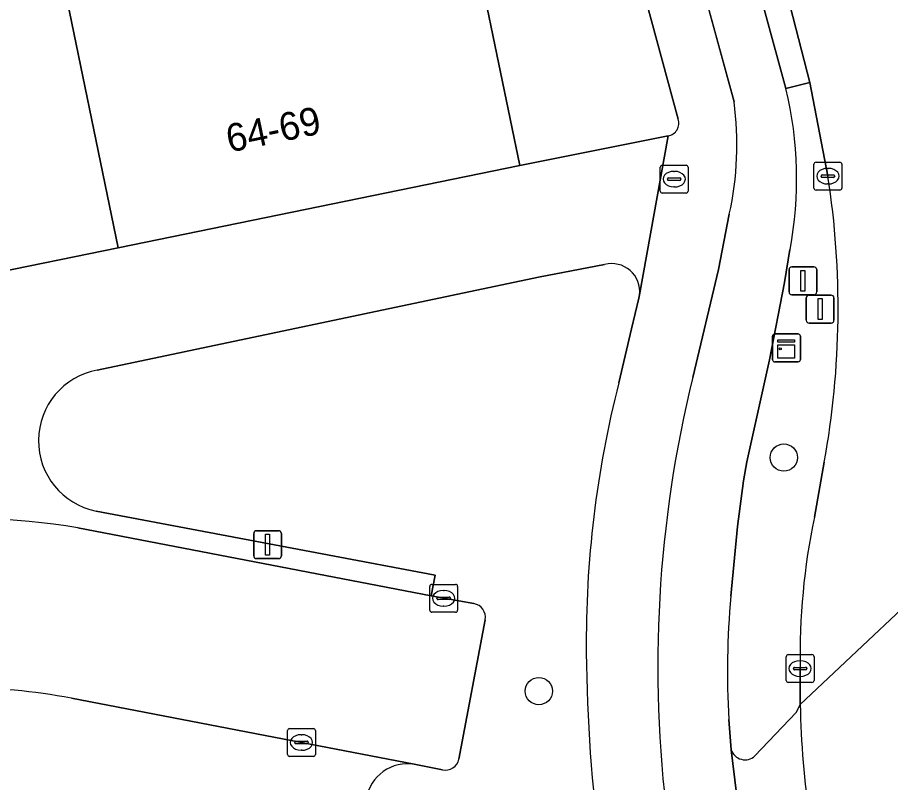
# Model space of a CAD drawing. Extents: x 162250 to 162661, y 380743 to 381606.
# Drawn here: x 162600.53 to 162631.84, y 380840.21 to 380867.66 of the extents above; entities that cross this region are included whole.
import ezdxf

# ---------------------------------------------------------------- set-up
doc = ezdxf.new("R2010")
doc.units = 0
for name, color, linetype in [('IMGEO_Berm_groen', 7, 'Continuous'), ('IMGEO_Berm_open', 7, 'Continuous'), ('IMGEO_Boom', 7, 'Continuous'), ('IMGEO_Brandkraan', 7, 'Continuous'), ('IMGEO_Erf', 7, 'Continuous'), ('IMGEO_Fietspad_gesloten', 7, 'Continuous'), ('IMGEO_Kast', 7, 'Continuous'), ('IMGEO_Kolk', 7, 'Continuous'), ('IMGEO_Lichtmast', 7, 'Continuous'), ('IMGEO_Pand', 7, 'Continuous'), ('IMGEO_Pand_nummerreeks', 7, 'Continuous'), ('IMGEO_Parkeervlak_open', 7, 'Continuous'), ('IMGEO_Rijbaan_lokaal_open', 7, 'Continuous'), ('IMGEO_Rijbaan_regionaal_gesloten', 7, 'Continuous'), ('IMGEO_Verkeersbordpaal', 7, 'Continuous'), ('IMGEO_Voetpad_open', 7, 'Continuous')]:
    doc.layers.add(name, color=color, linetype=linetype)

msp = doc.modelspace()

# ---------------------------------------------------------------- linework, layer by layer
at = {"layer": 'IMGEO_Berm_groen'}
for points in [[(162629.599, 380861.965), (162628.944, 380865.326), (162628.093, 380865.109)], [(162628.238, 380859.328), (162628.042, 380858.148), (162627.503, 380855.38), (162626.685, 380851.71), (162626.568, 380851.036), (162626.354, 380849.393), (162626.119, 380846.891)], [(162621.589, 380858.795), (162619.217, 380858.339), (162603.392, 380855.005)], [(162622.101, 380854.553), (162622.553, 380856.483), (162622.819, 380857.59), (162622.839, 380857.702)], [(162629.113, 380849.734), (162629.467, 380851.7)], [(162603.351, 380849.948), (162615.515, 380847.643), (162615.367, 380846.905), (162615.817, 380846.818), (162616.902, 380846.627)], [(162617.302, 380846.05), (162616.36, 380841.046)], [(162626.978, 380841.161), (162628.462, 380842.721), (162628.606, 380843.012), (162628.601, 380844.298)], [(162626.041, 380842.471), (162626.128, 380841.381)], [(162615.777, 380840.665), (162614.761, 380840.862)]]:
    msp.add_lwpolyline(points, dxfattribs=at)
for centre, radius, start, end in [((162614.644, 380861.879), 13.832, 349.3705, 13.5031), ((162598.973, 380857.225), 30.991, 349.7295, 8.797), ((162621.842, 380857.823), 1.005, 353.093, 104.5741), ((162603.858, 380852.473), 2.575, 100.4233, 258.6477), ((162658.392, 380845.259), 37.462, 165.6362, 180.6017), ((162653.087, 380844.734), 24.49, 168.2189, 181.0198), ((162655.464, 380844.162), 29.471, 174.6878, 183.2902), ((162616.82, 380846.143), 0.491, 349.1261, 80.3364), ((162677.445, 380845.318), 56.515, 180.4583, 187.747), ((162626.625, 380841.548), 0.524, 198.6227, 312.3552), ((162614.515, 380839.396), 1.486, 80.4672, 170.7157), ((162615.88, 380841.144), 0.49, 257.8966, 348.434)]:
    msp.add_arc(centre, radius, start, end, dxfattribs=at)
at = {"layer": 'IMGEO_Berm_open'}
msp.add_lwpolyline([(162623.965, 380883.775), (162619.411, 380900.399), (162618.527, 380900.159), (162628.093, 380865.109), (162628.944, 380865.326), (162628.244, 380868.06), (162627.92, 380869.249), (162626.435, 380874.703)], close=True, dxfattribs=at)
at = {"layer": 'IMGEO_Boom'}
for centre in [(162628.018, 380851.866), (162619.227, 380843.49)]:
    msp.add_circle(centre, 0.489, dxfattribs=at)
at = {"layer": 'IMGEO_Brandkraan'}
for p, q in [((162623.583, 380861.432), (162623.583, 380862.284)), ((162623.658, 380862.358), (162624.51, 380862.358)), ((162624.071, 380862.138), (162624.096, 380862.138)), ((162624.584, 380862.284), (162624.584, 380861.432)), ((162623.842, 380861.852), (162623.842, 380861.864)), ((162624.28, 380861.815), (162623.882, 380861.815)), ((162623.885, 380861.901), (162624.283, 380861.901)), ((162624.326, 380861.864), (162624.326, 380861.852)), ((162624.094, 380861.578), (162624.069, 380861.578)), ((162624.51, 380861.358), (162623.658, 380861.358))]:
    msp.add_line(p, q, dxfattribs=at)
for points in [[(162623.583, 380861.432), (162623.583, 380862.284)], [(162623.658, 380862.358), (162624.51, 380862.358)], [(162624.584, 380862.284), (162624.584, 380861.432)], [(162624.51, 380861.358), (162623.658, 380861.358)]]:
    msp.add_lwpolyline(points, dxfattribs=at)
for centre, radius, start, end in [((162623.66, 380862.282), 0.0765, 91.552, 178.448), ((162623.66, 380862.282), 0.0765, 91.552, 178.448), ((162624.508, 380862.282), 0.0765, 1.552, 88.448), ((162624.508, 380862.282), 0.0765, 1.552, 88.448), ((162623.882, 380861.861), 0.0403, 85.8775, 175.7526), ((162623.879, 380861.851), 0.0366, 178.938, 274.7102), ((162624.283, 380861.858), 0.043, 264.8664, 352.4533), ((162624.287, 380861.863), 0.0386, 1.7309, 96.639), ((162623.66, 380861.434), 0.0765, 181.552, 268.448), ((162623.66, 380861.434), 0.0765, 181.552, 268.448), ((162624.508, 380861.434), 0.0765, 271.552, 358.448), ((162624.508, 380861.434), 0.0765, 271.552, 358.448)]:
    msp.add_arc(centre, radius, start, end, dxfattribs=at)
for centre, major_axis, ratio, start_param, end_param in [((162624.07, 380861.858), (-0.387, 0.002), 0.722429, 4.712389, 7.853982), ((162624.095, 380861.858), (-0.39, 0.002), 0.717154, 1.570796, 4.712389)]:
    msp.add_ellipse(centre, major_axis=major_axis, ratio=ratio, start_param=start_param, end_param=end_param, dxfattribs=at)
at = {"layer": 'IMGEO_Erf'}
for points in [[(162624.224, 380864.011), (162617.599, 380888.46)], [(162616.411, 380872.69), (162618.544, 380862.342), (162623.868, 380863.414)]]:
    msp.add_lwpolyline(points, dxfattribs=at)
msp.add_arc((162623.803, 380863.857), 0.448, 278.3341, 20.0494, dxfattribs=at)
at = {"layer": 'IMGEO_Fietspad_gesloten'}
for points in [[(162508.721, 381294.058), (162520.721, 381250), (162524.95, 381234.475), (162526.439, 381228.987), (162532.158, 381208.274), (162537.019, 381190.487), (162538.98, 381183.33), (162547.107, 381153.663), (162547.143, 381153.533), (162549.695, 381144.216), (162549.852, 381143.643), (162552.836, 381132.744), (162558.72, 381111.249), (162561.27, 381101.934), (162571.085, 381066.091), (162575.392, 381050.363), (162582.804, 381023.355), (162585.413, 381013.87), (162586.64, 381009.407), (162588.336, 381003.241), (162600.985, 380956.955), (162611.456, 380918.623), (162619.54, 380889.111), (162626.231, 380864.638)], [(162628.093, 380865.109), (162618.527, 380900.159), (162616.074, 380909.136), (162614.869, 380913.477), (162613.482, 380918.571), (162613.149, 380919.833), (162611.747, 380924.889), (162608.338, 380937.386)], [(162626.06, 380860.596), (162625.678, 380858.622), (162624.749, 380854.747)], [(162626.119, 380846.891), (162626.354, 380849.393), (162626.568, 380851.036), (162626.685, 380851.71), (162627.503, 380855.38), (162628.042, 380858.148), (162628.238, 380859.328)], [(162626.638, 380837.167), (162626.128, 380841.381), (162626.041, 380842.471)]]:
    msp.add_lwpolyline(points, dxfattribs=at)
for centre, radius, start, end in [((162614.644, 380861.879), 13.832, 349.3705, 13.5031), ((162614.662, 380863.103), 11.671, 347.5963, 7.5587), ((162667.153, 380844.362), 43.657, 166.2383, 187.2623), ((162655.464, 380844.162), 29.471, 174.6878, 183.2902)]:
    msp.add_arc(centre, radius, start, end, dxfattribs=at)
at = {"layer": 'IMGEO_Kast'}
for p, q in [((162627.61, 380855.378), (162627.61, 380856.219)), ((162627.61, 380856.219), (162627.61, 380855.378)), ((162627.685, 380856.303), (162628.526, 380856.303)), ((162628.526, 380856.303), (162627.685, 380856.303)), ((162628.61, 380856.228), (162628.61, 380855.387)), ((162628.61, 380855.387), (162628.61, 380856.228)), ((162628.535, 380855.303), (162627.694, 380855.303)), ((162627.694, 380855.303), (162628.535, 380855.303))]:
    msp.add_line(p, q, dxfattribs=at)
for points in [[(162627.805, 380856.093), (162628.405, 380856.093), (162628.405, 380856.008), (162627.805, 380856.008), (162627.805, 380856.093)], [(162627.805, 380855.918), (162628.405, 380855.918), (162628.405, 380855.429), (162627.805, 380855.429), (162627.805, 380855.918)]]:
    msp.add_lwpolyline(points, dxfattribs=at)
msp.add_circle((162627.889, 380855.767), 0.0377, dxfattribs=at)
for centre, start, end in [((162627.688, 380856.225), 92.4484, 184.2845), ((162627.688, 380856.225), 92.4484, 184.2845), ((162628.532, 380856.225), 2.4484, 94.2845), ((162628.532, 380856.225), 2.4484, 94.2845), ((162627.688, 380855.381), 182.4484, 274.2845), ((162627.688, 380855.381), 182.4484, 274.2845), ((162628.532, 380855.381), 272.4484, 4.2845), ((162628.532, 380855.381), 272.4484, 4.2845)]:
    msp.add_arc(centre, 0.0779, start, end, dxfattribs=at)
at = {"layer": 'IMGEO_Kolk'}
for p, q in [((162629.173, 380862.465), (162630.025, 380862.465)), ((162629.098, 380861.539), (162629.098, 380862.391)), ((162629.586, 380862.245), (162629.611, 380862.245)), ((162630.099, 380862.391), (162630.099, 380861.539)), ((162629.357, 380861.959), (162629.357, 380861.971)), ((162629.795, 380861.922), (162629.397, 380861.922)), ((162629.4, 380862.008), (162629.798, 380862.008)), ((162629.841, 380861.971), (162629.841, 380861.959)), ((162630.025, 380861.465), (162629.173, 380861.465)), ((162629.609, 380861.685), (162629.584, 380861.685)), ((162615.316, 380846.392), (162615.316, 380847.244)), ((162615.391, 380847.318), (162616.243, 380847.318)), ((162615.804, 380847.098), (162615.829, 380847.098)), ((162616.317, 380847.244), (162616.317, 380846.392)), ((162615.575, 380846.812), (162615.575, 380846.824)), ((162616.013, 380846.775), (162615.615, 380846.775)), ((162615.618, 380846.861), (162616.016, 380846.861)), ((162616.059, 380846.824), (162616.059, 380846.812)), ((162615.827, 380846.538), (162615.802, 380846.538)), ((162616.243, 380846.318), (162615.391, 380846.318)), ((162628.1, 380843.872), (162628.1, 380844.724)), ((162628.175, 380844.798), (162629.027, 380844.798)), ((162628.588, 380844.578), (162628.613, 380844.578)), ((162629.101, 380844.724), (162629.101, 380843.872)), ((162628.359, 380844.292), (162628.359, 380844.304)), ((162628.797, 380844.255), (162628.399, 380844.255)), ((162628.402, 380844.341), (162628.8, 380844.341)), ((162628.843, 380844.304), (162628.843, 380844.292)), ((162628.611, 380844.018), (162628.586, 380844.018)), ((162629.027, 380843.798), (162628.175, 380843.798)), ((162610.214, 380841.219), (162610.214, 380842.071)), ((162610.289, 380842.145), (162611.141, 380842.145)), ((162611.215, 380842.071), (162611.215, 380841.219)), ((162610.702, 380841.925), (162610.727, 380841.925)), ((162610.473, 380841.639), (162610.473, 380841.651)), ((162610.911, 380841.602), (162610.513, 380841.602)), ((162610.516, 380841.688), (162610.914, 380841.688)), ((162610.957, 380841.651), (162610.957, 380841.639)), ((162611.141, 380841.145), (162610.289, 380841.145)), ((162610.725, 380841.365), (162610.7, 380841.365))]:
    msp.add_line(p, q, dxfattribs=at)
for points in [[(162629.173, 380862.465), (162630.025, 380862.465)], [(162629.098, 380861.539), (162629.098, 380862.391)], [(162630.099, 380862.391), (162630.099, 380861.539)], [(162630.025, 380861.465), (162629.173, 380861.465)], [(162615.316, 380846.392), (162615.316, 380847.244)], [(162615.391, 380847.318), (162616.243, 380847.318)], [(162616.317, 380847.244), (162616.317, 380846.392)], [(162616.243, 380846.318), (162615.391, 380846.318)], [(162628.1, 380843.872), (162628.1, 380844.724)], [(162628.175, 380844.798), (162629.027, 380844.798)], [(162629.101, 380844.724), (162629.101, 380843.872)], [(162629.027, 380843.798), (162628.175, 380843.798)], [(162610.214, 380841.219), (162610.214, 380842.071)], [(162610.289, 380842.145), (162611.141, 380842.145)], [(162611.215, 380842.071), (162611.215, 380841.219)], [(162611.141, 380841.145), (162610.289, 380841.145)]]:
    msp.add_lwpolyline(points, dxfattribs=at)
for centre, radius, start, end in [((162629.175, 380862.389), 0.0765, 91.552, 178.448), ((162629.175, 380862.389), 0.0765, 91.552, 178.448), ((162630.023, 380862.389), 0.0765, 1.552, 88.448), ((162630.023, 380862.389), 0.0765, 1.552, 88.448), ((162629.397, 380861.968), 0.0403, 85.8775, 175.7526), ((162629.394, 380861.958), 0.0366, 178.938, 274.7102), ((162629.798, 380861.965), 0.043, 264.8664, 352.4533), ((162629.802, 380861.97), 0.0386, 1.7309, 96.639), ((162629.175, 380861.541), 0.0765, 181.552, 268.448), ((162629.175, 380861.541), 0.0765, 181.552, 268.448), ((162630.023, 380861.541), 0.0765, 271.552, 358.448), ((162630.023, 380861.541), 0.0765, 271.552, 358.448), ((162615.393, 380847.242), 0.0765, 91.552, 178.448), ((162615.393, 380847.242), 0.0765, 91.552, 178.448), ((162616.241, 380847.242), 0.0765, 1.552, 88.448), ((162616.241, 380847.242), 0.0765, 1.552, 88.448), ((162615.615, 380846.821), 0.0403, 85.8775, 175.7526), ((162615.612, 380846.811), 0.0366, 178.938, 274.7102), ((162616.016, 380846.818), 0.043, 264.8664, 352.4533), ((162616.02, 380846.823), 0.0386, 1.7309, 96.639), ((162615.393, 380846.394), 0.0765, 181.552, 268.448), ((162615.393, 380846.394), 0.0765, 181.552, 268.448), ((162616.241, 380846.394), 0.0765, 271.552, 358.448), ((162616.241, 380846.394), 0.0765, 271.552, 358.448), ((162628.177, 380844.722), 0.0765, 91.552, 178.448), ((162628.177, 380844.722), 0.0765, 91.552, 178.448), ((162629.025, 380844.722), 0.0765, 1.552, 88.448), ((162629.025, 380844.722), 0.0765, 1.552, 88.448), ((162628.399, 380844.301), 0.0403, 85.8775, 175.7526), ((162628.396, 380844.291), 0.0366, 178.938, 274.7102), ((162628.8, 380844.298), 0.043, 264.8664, 352.4533), ((162628.804, 380844.303), 0.0386, 1.7309, 96.639), ((162628.177, 380843.874), 0.0765, 181.552, 268.448), ((162628.177, 380843.874), 0.0765, 181.552, 268.448), ((162629.025, 380843.874), 0.0765, 271.552, 358.448), ((162629.025, 380843.874), 0.0765, 271.552, 358.448), ((162610.291, 380842.069), 0.0765, 91.552, 178.448), ((162610.291, 380842.069), 0.0765, 91.552, 178.448), ((162611.139, 380842.069), 0.0765, 1.552, 88.448), ((162611.139, 380842.069), 0.0765, 1.552, 88.448), ((162610.513, 380841.648), 0.0403, 85.8775, 175.7526), ((162610.51, 380841.638), 0.0366, 178.938, 274.7102), ((162610.914, 380841.645), 0.043, 264.8664, 352.4533), ((162610.918, 380841.65), 0.0386, 1.7309, 96.639), ((162610.291, 380841.221), 0.0765, 181.552, 268.448), ((162610.291, 380841.221), 0.0765, 181.552, 268.448), ((162611.139, 380841.221), 0.0765, 271.552, 358.448), ((162611.139, 380841.221), 0.0765, 271.552, 358.448)]:
    msp.add_arc(centre, radius, start, end, dxfattribs=at)
for centre, major_axis, ratio, start_param, end_param in [((162629.585, 380861.965), (-0.387, 0.002), 0.722429, 4.712389, 7.853982), ((162629.61, 380861.965), (-0.39, 0.002), 0.717154, 1.570796, 4.712389), ((162615.803, 380846.818), (-0.387, 0.002), 0.722429, 4.712389, 7.853982), ((162615.828, 380846.818), (-0.39, 0.002), 0.717154, 1.570796, 4.712389), ((162628.587, 380844.298), (-0.387, 0.002), 0.722429, 4.712389, 7.853982), ((162628.612, 380844.298), (-0.39, 0.002), 0.717154, 1.570796, 4.712389), ((162610.701, 380841.645), (-0.387, 0.002), 0.722429, 4.712389, 7.853982), ((162610.726, 380841.645), (-0.39, 0.002), 0.717154, 1.570796, 4.712389)]:
    msp.add_ellipse(centre, major_axis=major_axis, ratio=ratio, start_param=start_param, end_param=end_param, dxfattribs=at)
at = {"layer": 'IMGEO_Lichtmast'}
for p, q in [((162628.823, 380856.795), (162628.823, 380857.595)), ((162628.823, 380857.595), (162628.823, 380856.795)), ((162628.923, 380857.695), (162629.713, 380857.695)), ((162629.713, 380857.695), (162628.923, 380857.695)), ((162629.813, 380857.595), (162629.813, 380856.795)), ((162629.813, 380856.795), (162629.813, 380857.595)), ((162629.713, 380856.695), (162628.923, 380856.695)), ((162628.923, 380856.695), (162629.713, 380856.695)), ((162609.004, 380848.343), (162609.004, 380849.143)), ((162609.004, 380849.143), (162609.004, 380848.343)), ((162609.104, 380849.243), (162609.894, 380849.243)), ((162609.894, 380849.243), (162609.104, 380849.243)), ((162609.994, 380849.143), (162609.994, 380848.343)), ((162609.994, 380848.343), (162609.994, 380849.143)), ((162609.894, 380848.243), (162609.104, 380848.243)), ((162609.104, 380848.243), (162609.894, 380848.243))]:
    msp.add_line(p, q, dxfattribs=at)
for points in [[(162629.243, 380857.57), (162629.393, 380857.57), (162629.393, 380856.82), (162629.243, 380856.82), (162629.243, 380857.57)], [(162609.424, 380849.118), (162609.574, 380849.118), (162609.574, 380848.368), (162609.424, 380848.368), (162609.424, 380849.118)]]:
    msp.add_lwpolyline(points, dxfattribs=at)
for centre, start, end in [((162628.923, 380857.595), 90, 180), ((162628.923, 380857.595), 90, 180), ((162629.713, 380857.595), 0, 90), ((162629.713, 380857.595), 360, 90), ((162628.923, 380856.795), 180, 270), ((162628.923, 380856.795), 180, 270), ((162629.713, 380856.795), 270, 0), ((162629.713, 380856.795), 270, 0), ((162609.104, 380849.143), 90, 180), ((162609.104, 380849.143), 90, 180), ((162609.894, 380849.143), 0, 90), ((162609.894, 380849.143), 360, 90), ((162609.104, 380848.343), 180, 270), ((162609.104, 380848.343), 180, 270), ((162609.894, 380848.343), 270, 0), ((162609.894, 380848.343), 270, 0)]:
    msp.add_arc(centre, 0.1, start, end, dxfattribs=at)
at = {"layer": 'IMGEO_Pand'}
for points in [[(162604.143, 380859.394), (162618.544, 380862.342), (162616.411, 380872.69), (162602.001, 380869.784)], [(162587.591, 380866.878), (162589.741, 380856.447), (162604.143, 380859.394), (162602.001, 380869.784)]]:
    msp.add_lwpolyline(points, close=True, dxfattribs=at)
at = {"layer": 'IMGEO_Parkeervlak_open'}
msp.add_lwpolyline([(162614.761, 380840.862), (162610.715, 380841.645), (162602.462, 380843.231)], dxfattribs=at)
for centre, radius, start, end in [((162598.662, 380823.474), 20.12, 79.1132, 102.5419), ((162614.515, 380839.396), 1.486, 80.4672, 170.7157)]:
    msp.add_arc(centre, radius, start, end, dxfattribs=at)
at = {"layer": 'IMGEO_Rijbaan_lokaal_open'}
for points in [[(162616.902, 380846.627), (162615.817, 380846.818), (162615.367, 380846.905), (162602.692, 380849.343)], [(162616.36, 380841.046), (162617.302, 380846.05)], [(162602.462, 380843.231), (162610.715, 380841.645), (162614.761, 380840.862), (162615.777, 380840.665)]]:
    msp.add_lwpolyline(points, dxfattribs=at)
for centre, radius, start, end in [((162598.528, 380824.899), 24.796, 80.3325, 96.5557), ((162616.82, 380846.143), 0.491, 349.1261, 80.3364), ((162598.662, 380823.474), 20.12, 79.1132, 102.5419), ((162615.88, 380841.144), 0.49, 257.8966, 348.434)]:
    msp.add_arc(centre, radius, start, end, dxfattribs=at)
at = {"layer": 'IMGEO_Rijbaan_regionaal_gesloten'}
for points in [[(162635.693, 380863.92), (162633.811, 380870.819), (162627.92, 380869.249), (162628.244, 380868.06), (162628.944, 380865.326), (162629.599, 380861.965)], [(162629.467, 380851.7), (162629.113, 380849.734)], [(162628.601, 380844.298), (162628.606, 380843.012), (162634.471, 380848.538), (162637.045, 380850.963)], [(162637.693, 380843.086), (162637.296, 380846.974), (162637.045, 380850.963), (162634.471, 380848.538), (162628.606, 380843.012)]]:
    msp.add_lwpolyline(points, dxfattribs=at)
for centre, radius, start, end in [((162598.973, 380857.225), 30.991, 349.7295, 8.797), ((162653.087, 380844.734), 24.49, 168.2189, 181.0198), ((162658.415, 380843.446), 29.812, 180.8333, 188.8403)]:
    msp.add_arc(centre, radius, start, end, dxfattribs=at)
at = {"layer": 'IMGEO_Verkeersbordpaal'}
for p, q in [((162628.306, 380858.711), (162629.096, 380858.711)), ((162629.096, 380858.711), (162628.306, 380858.711)), ((162628.206, 380857.811), (162628.206, 380858.611)), ((162628.206, 380858.611), (162628.206, 380857.811)), ((162629.196, 380858.611), (162629.196, 380857.811)), ((162629.196, 380857.811), (162629.196, 380858.611)), ((162629.096, 380857.711), (162628.306, 380857.711)), ((162628.306, 380857.711), (162629.096, 380857.711))]:
    msp.add_line(p, q, dxfattribs=at)
msp.add_lwpolyline([(162628.626, 380858.586), (162628.776, 380858.586), (162628.776, 380857.836), (162628.626, 380857.836), (162628.626, 380858.586)], dxfattribs=at)
for centre, start, end in [((162628.306, 380858.611), 90, 180), ((162628.306, 380858.611), 90, 180), ((162629.096, 380858.611), 0, 90), ((162629.096, 380858.611), 360, 90), ((162628.306, 380857.811), 180, 270), ((162628.306, 380857.811), 180, 270), ((162629.096, 380857.811), 270, 0), ((162629.096, 380857.811), 270, 0)]:
    msp.add_arc(centre, 0.1, start, end, dxfattribs=at)
at = {"layer": 'IMGEO_Voetpad_open'}
for points in [[(162626.231, 380864.638), (162619.54, 380889.111), (162611.456, 380918.623), (162600.985, 380956.955), (162588.336, 381003.241), (162586.64, 381009.407), (162585.413, 381013.87), (162582.804, 381023.355), (162575.392, 381050.363), (162571.085, 381066.091), (162561.27, 381101.934)], [(162590.725, 380986.876), (162591.812, 380983.319), (162592.746, 380979.796), (162593.598, 380976.705), (162599.376, 380955.751), (162610.123, 380915.626), (162617.13, 380890.168), (162617.599, 380888.46), (162624.224, 380864.011)], [(162622.839, 380857.702), (162623.868, 380863.414), (162618.544, 380862.342), (162604.143, 380859.394), (162589.741, 380856.447), (162575.34, 380853.499), (162561.354, 380850.637), (162561.385, 380850.49), (162560.85, 380850.377), (162562.236, 380843.394)], [(162623.868, 380863.414), (162622.839, 380857.702), (162622.819, 380857.59), (162622.553, 380856.483), (162622.101, 380854.553)], [(162624.749, 380854.747), (162625.678, 380858.622), (162626.06, 380860.596)], [(162603.392, 380855.005), (162619.217, 380858.339), (162621.589, 380858.795)], [(162602.692, 380849.343), (162615.367, 380846.905), (162615.515, 380847.643), (162603.351, 380849.948)], [(162628.606, 380843.012), (162628.462, 380842.721), (162626.978, 380841.161)], [(162626.128, 380841.381), (162626.638, 380837.167), (162626.742, 380837.408), (162628.307, 380839.052)]]:
    msp.add_lwpolyline(points, dxfattribs=at)
for centre, radius, start, end in [((162614.662, 380863.103), 11.671, 347.5963, 7.5587), ((162623.803, 380863.857), 0.448, 278.3341, 20.0494), ((162621.842, 380857.823), 1.005, 353.093, 104.5741), ((162603.858, 380852.473), 2.575, 100.4233, 258.6477), ((162667.153, 380844.362), 43.657, 166.2383, 187.2623), ((162658.392, 380845.259), 37.462, 165.6362, 180.6017), ((162598.528, 380824.899), 24.796, 80.3325, 96.5557), ((162677.445, 380845.318), 56.515, 180.4583, 187.747), ((162658.415, 380843.446), 29.812, 180.8333, 188.8403), ((162626.625, 380841.548), 0.524, 198.6227, 312.3552)]:
    msp.add_arc(centre, radius, start, end, dxfattribs=at)

# ---------------------------------------------------------------- texts
at = {"layer": 'IMGEO_Pand_nummerreeks'}
msp.add_text('64-69', height=1, rotation=11.6949, dxfattribs=at).set_placement((162608.127, 380862.809))

doc.saveas('drawing.dxf')
